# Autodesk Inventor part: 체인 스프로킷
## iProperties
Created: 2013-01
Part Number: 체인 스프로킷
Material: Steel
Document SubType Name: Modeling
Designer: KYOUNG IL JANG
Density: 1 g/cm^3
CustomPartVersion: 1
Company: 한국ATC센터
Author: KYOUNG IL JANG
